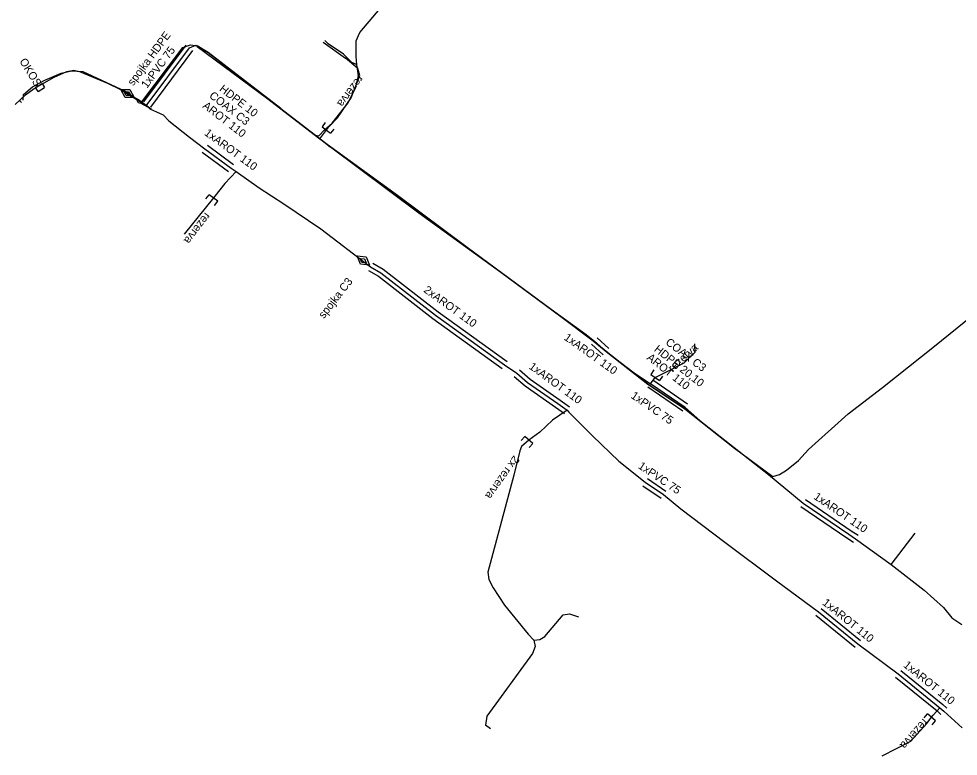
# Model space of a CAD drawing. Extents: x -651943 to -618711, y -1138561 to -1100552.
# Drawn here: x -648800.9 to -648712.9, y -1112060.5 to -1111991.5 of the extents above; entities that cross this region are included whole.
import ezdxf

# ---------------------------------------------------------------- set-up
doc = ezdxf.new("R2010")
doc.units = 0
for name, color, linetype in [('KT optika', 7, 'Continuous'), ('KT trasa', 7, 'Continuous'), ('KT zařízení', 7, 'Continuous')]:
    doc.layers.add(name, color=color, linetype=linetype)

# ---------------------------------------------------------------- blocks, each defined once
blk = doc.blocks.new('TVSPO_1')
at = {"layer": 'KT zařízení'}
for p, q in [((-0.074, 0.0016), (-0.0005, 0.0439)), ((-0.0005, -0.0409), (-0.074, 0.0016)), ((-0.0353, -0.0001), (0, 0.0203)), ((-0.0005, 0.0439), (0.0728, 0.0015)), ((0.0728, 0.0015), (-0.0005, -0.0409)), ((0, 0.0203), (0.0353, 0.0001)), ((0.0353, 0.0001), (0, -0.0204)), ((0, -0.0204), (-0.0353, -0.0001))]:
    blk.add_line(p, q, dxfattribs=at)
blk = doc.blocks.new('TVREZ')
at = {"layer": 'KT zařízení'}
for p, q in [((-0.05, 0.05), (0, 0.05)), ((0, -0.05), (0, 0.05)), ((-0.05, -0.05), (0, -0.05))]:
    blk.add_line(p, q, dxfattribs=at)

msp = doc.modelspace()

# ---------------------------------------------------------------- linework, layer by layer
at = {"layer": 'KT optika'}
for p, q in [((-648768.94, -1111992.78), (-648764.88, -1111988)), ((-648769.26, -1111993.55), (-648768.94, -1111992.78)), ((-648789.46, -1111999.38), (-648785.51, -1111994.17)), ((-648785.51, -1111994.17), (-648784.78, -1111993.94)), ((-648784.78, -1111993.94), (-648784.16, -1111994.01)), ((-648784.16, -1111994.01), (-648783.14, -1111994.66)), ((-648772.219, -1111993.533), (-648771.91, -1111993.85)), ((-648770.46, -1111994.81), (-648771.91, -1111993.85)), ((-648769.26, -1111995.02), (-648769.26, -1111993.55)), ((-648783.14, -1111994.66), (-648776.34, -1111999.9)), ((-648769.68, -1111995.57), (-648770.46, -1111994.81)), ((-648769.22, -1111995.76), (-648769.26, -1111995.02)), ((-648769.22, -1111995.76), (-648769.68, -1111995.57)), ((-648769.07, -1111996.82), (-648769.22, -1111995.76)), ((-648798.44, -1111997.23), (-648796.9, -1111996.58)), ((-648796.9, -1111996.58), (-648795.93, -1111996.35)), ((-648795.93, -1111996.35), (-648794.87, -1111996.44)), ((-648794.87, -1111996.44), (-648790.92, -1111998.27)), ((-648769.29, -1111997.88), (-648769.07, -1111996.82)), ((-648799.61, -1111997.87), (-648798.44, -1111997.23)), ((-648800.48, -1111999.12), (-648800.45, -1111998.58)), ((-648800.45, -1111998.58), (-648799.61, -1111997.87)), ((-648790.92, -1111998.27), (-648789.93, -1111998.92)), ((-648770.01, -1111999.37), (-648769.29, -1111997.88)), ((-648789.93, -1111998.92), (-648789.69, -1111999.33)), ((-648789.93, -1111998.92), (-648789.68, -1111999.05)), ((-648789.69, -1111999.33), (-648789.46, -1111999.38)), ((-648789.68, -1111999.05), (-648788.48, -1111999.91)), ((-648771.51, -1112001.26), (-648770.01, -1111999.37)), ((-648776.34, -1111999.9), (-648773.09, -1112002.39)), ((-648772.25, -1112001.89), (-648771.51, -1112001.26)), ((-648772.78, -1112002.44), (-648772.25, -1112001.89)), ((-648773.09, -1112002.39), (-648771.7, -1112003.47)), ((-648773.09, -1112002.39), (-648772.78, -1112002.44)), ((-648771.7, -1112003.47), (-648771.69, -1112003.47)), ((-648771.69, -1112003.47), (-648763.4, -1112009.67)), ((-648763.4, -1112009.67), (-648755.73, -1112015.2)), ((-648755.73, -1112015.2), (-648750.09, -1112019.36)), ((-648715.08, -1112022.15), (-648705.95, -1112014.71)), ((-648750.09, -1112019.36), (-648747.06, -1112021.63)), ((-648747.06, -1112021.63), (-648745.69, -1112022.75)), ((-648719.96, -1112026), (-648715.08, -1112022.15)), ((-648745.69, -1112022.75), (-648741.96, -1112025.7)), ((-648741.96, -1112025.7), (-648738.48, -1112028)), ((-648723.19, -1112028.48), (-648719.96, -1112026)), ((-648738.48, -1112028), (-648733.82, -1112031.7)), ((-648726.89, -1112031.82), (-648723.19, -1112028.48)), ((-648733.82, -1112031.7), (-648730.23, -1112034.35)), ((-648727.84, -1112032.84), (-648726.89, -1112031.82)), ((-648728.96, -1112033.73), (-648727.84, -1112032.84)), ((-648729.63, -1112034.15), (-648728.96, -1112033.73)), ((-648730.23, -1112034.35), (-648729.63, -1112034.15))]:
    msp.add_line(p, q, dxfattribs=at)
at = {"layer": 'KT trasa'}
for p, q in [((-648768.94, -1111992.78), (-648764.88, -1111988)), ((-648769.26, -1111993.55), (-648768.94, -1111992.78)), ((-648789.46, -1111999.38), (-648785.51, -1111994.17)), ((-648788.84, -1111999.51), (-648784.89, -1111994.21)), ((-648785.51, -1111994.17), (-648784.78, -1111993.94)), ((-648784.89, -1111994.21), (-648784.31, -1111993.97)), ((-648784.78, -1111993.94), (-648784.16, -1111994.01)), ((-648784.31, -1111993.97), (-648784.18, -1111994.1)), ((-648784.18, -1111994.1), (-648777.66, -1111998.89)), ((-648784.16, -1111994.01), (-648783.14, -1111994.66)), ((-648772.366, -1111993.676), (-648770.28, -1111995.18)), ((-648772.219, -1111993.533), (-648771.91, -1111993.85)), ((-648770.46, -1111994.81), (-648771.91, -1111993.85)), ((-648769.26, -1111995.02), (-648769.26, -1111993.55)), ((-648783.14, -1111994.66), (-648776.34, -1111999.9)), ((-648769.68, -1111995.57), (-648770.46, -1111994.81)), ((-648769.22, -1111995.76), (-648769.26, -1111995.02)), ((-648769.11, -1111996.14), (-648770.28, -1111995.18)), ((-648769.22, -1111995.76), (-648769.68, -1111995.57)), ((-648769.07, -1111996.82), (-648769.22, -1111995.76)), ((-648798.44, -1111997.23), (-648796.9, -1111996.58)), ((-648797.56, -1111996.95), (-648796.37, -1111996.44)), ((-648796.9, -1111996.58), (-648795.93, -1111996.35)), ((-648796.37, -1111996.44), (-648795.71, -1111996.3)), ((-648795.93, -1111996.35), (-648794.87, -1111996.44)), ((-648795.71, -1111996.3), (-648795.18, -1111996.42)), ((-648795.18, -1111996.42), (-648792.57, -1111997.53)), ((-648794.87, -1111996.44), (-648790.92, -1111998.27)), ((-648769.74, -1111998.9), (-648768.94, -1111996.79)), ((-648769.29, -1111997.88), (-648769.07, -1111996.82)), ((-648768.94, -1111996.79), (-648769.11, -1111996.14)), ((-648799.61, -1111997.87), (-648798.44, -1111997.23)), ((-648799.43, -1111998.03), (-648797.56, -1111996.95)), ((-648792.57, -1111997.53), (-648791.28, -1111998.14)), ((-648801.22, -1111999.52), (-648800.26, -1111998.61)), ((-648800.48, -1111999.12), (-648800.45, -1111998.58)), ((-648800.45, -1111998.58), (-648799.61, -1111997.87)), ((-648800.26, -1111998.61), (-648799.43, -1111998.03)), ((-648791.28, -1111998.14), (-648789.41, -1111999.29)), ((-648790.92, -1111998.27), (-648789.93, -1111998.92)), ((-648770.01, -1111999.37), (-648769.29, -1111997.88)), ((-648800.815, -1111999.136), (-648800.621, -1111999.34)), ((-648789.93, -1111998.92), (-648789.69, -1111999.33)), ((-648789.93, -1111998.92), (-648789.68, -1111999.05)), ((-648789.69, -1111999.33), (-648789.46, -1111999.38)), ((-648789.68, -1111999.05), (-648788.48, -1111999.91)), ((-648789.41, -1111999.29), (-648788.92, -1111999.62)), ((-648788.92, -1111999.62), (-648788.84, -1111999.51)), ((-648777.66, -1111998.89), (-648772.67, -1112002.74)), ((-648771.51, -1112001.26), (-648770.01, -1111999.37)), ((-648771.01, -1112000.76), (-648769.74, -1111998.9)), ((-648788.92, -1111999.62), (-648788.59, -1111999.92)), ((-648788.59, -1111999.92), (-648787.65, -1112000.37)), ((-648787.65, -1112000.37), (-648787.35, -1112000.48)), ((-648776.34, -1111999.9), (-648773.09, -1112002.39)), ((-648787.35, -1112000.48), (-648786.83, -1112001.05)), ((-648786.83, -1112001.05), (-648784.9, -1112002.57)), ((-648772.25, -1112001.89), (-648771.51, -1112001.26)), ((-648771.83, -1112001.59), (-648771.01, -1112000.76)), ((-648772.78, -1112002.44), (-648772.25, -1112001.89)), ((-648772.67, -1112002.74), (-648771.83, -1112001.59)), ((-648784.9, -1112002.57), (-648783.45, -1112003.66)), ((-648773.09, -1112002.39), (-648771.7, -1112003.47)), ((-648773.09, -1112002.39), (-648772.78, -1112002.44)), ((-648772.67, -1112002.74), (-648765.41, -1112008.01)), ((-648783.45, -1112003.66), (-648780.99, -1112005.46)), ((-648771.7, -1112003.47), (-648771.69, -1112003.47)), ((-648771.69, -1112003.47), (-648763.4, -1112009.67)), ((-648780.99, -1112005.46), (-648780.51, -1112005.78)), ((-648780.51, -1112005.78), (-648781.57, -1112006.92)), ((-648780.51, -1112005.78), (-648778.35, -1112007.33)), ((-648781.57, -1112006.92), (-648782.52, -1112008.11)), ((-648778.35, -1112007.33), (-648776.06, -1112008.82)), ((-648782.644, -1112008.263), (-648785.384, -1112011.651)), ((-648782.52, -1112008.11), (-648782.644, -1112008.263)), ((-648765.41, -1112008.01), (-648758.89, -1112012.87)), ((-648776.06, -1112008.82), (-648772.58, -1112011.14)), ((-648763.4, -1112009.67), (-648755.73, -1112015.2)), ((-648772.58, -1112011.14), (-648767.92, -1112014.71)), ((-648758.89, -1112012.87), (-648751, -1112018.66)), ((-648767.92, -1112014.71), (-648766.96, -1112015.26)), ((-648766.96, -1112015.26), (-648761.84, -1112019.24)), ((-648755.73, -1112015.2), (-648750.09, -1112019.36)), ((-648715.08, -1112022.15), (-648705.95, -1112014.71)), ((-648751, -1112018.66), (-648747.74, -1112021.06)), ((-648761.84, -1112019.24), (-648755.37, -1112023.89)), ((-648750.09, -1112019.36), (-648747.06, -1112021.63)), ((-648747.74, -1112021.06), (-648746.95, -1112021.66)), ((-648747.06, -1112021.63), (-648745.69, -1112022.75)), ((-648746.95, -1112021.66), (-648745.86, -1112022.64)), ((-648737.51, -1112022.69), (-648737.537, -1112021.905)), ((-648719.96, -1112026), (-648715.08, -1112022.15)), ((-648745.86, -1112022.64), (-648743.23, -1112024.64)), ((-648745.69, -1112022.75), (-648741.96, -1112025.7)), ((-648738.56, -1112023.7), (-648737.51, -1112022.69)), ((-648755.37, -1112023.89), (-648754.22, -1112024.67)), ((-648740.27, -1112024.58), (-648738.56, -1112023.7)), ((-648754.22, -1112024.67), (-648753.21, -1112025.53)), ((-648743.23, -1112024.64), (-648741.71, -1112025.65)), ((-648741.71, -1112025.65), (-648741.26, -1112025.06)), ((-648741.26, -1112025.06), (-648740.27, -1112024.58)), ((-648753.21, -1112025.53), (-648750.38, -1112027.51)), ((-648741.96, -1112025.7), (-648738.48, -1112028)), ((-648738.46, -1112027.89), (-648741.71, -1112025.65)), ((-648723.19, -1112028.48), (-648719.96, -1112026)), ((-648750.38, -1112027.51), (-648749.52, -1112028.13)), ((-648749.52, -1112028.13), (-648750.88, -1112029.07)), ((-648749.52, -1112028.13), (-648749.35, -1112028.3)), ((-648749.35, -1112028.3), (-648747.13, -1112030.54)), ((-648738.48, -1112028), (-648733.82, -1112031.7)), ((-648738.46, -1112027.89), (-648737.08, -1112029.09)), ((-648726.89, -1112031.82), (-648723.19, -1112028.48)), ((-648750.88, -1112029.07), (-648752.06, -1112030.19)), ((-648737.08, -1112029.09), (-648730.66, -1112034.16)), ((-648752.06, -1112030.19), (-648753.11, -1112030.93)), ((-648753.11, -1112030.93), (-648753.8, -1112031.53)), ((-648747.13, -1112030.54), (-648744.68, -1112032.91)), ((-648753.94, -1112031.92), (-648754.5, -1112034.2)), ((-648753.8, -1112031.53), (-648753.94, -1112031.92)), ((-648733.82, -1112031.7), (-648730.23, -1112034.35)), ((-648727.84, -1112032.84), (-648726.89, -1112031.82)), ((-648744.68, -1112032.91), (-648742.21, -1112034.87)), ((-648728.96, -1112033.73), (-648727.84, -1112032.84)), ((-648729.63, -1112034.15), (-648728.96, -1112033.73)), ((-648754.5, -1112034.2), (-648756.93, -1112043.29)), ((-648730.66, -1112034.16), (-648727.39, -1112036.83)), ((-648730.23, -1112034.35), (-648729.63, -1112034.15)), ((-648742.21, -1112034.87), (-648740.49, -1112036.03)), ((-648740.49, -1112036.03), (-648738.85, -1112037.37)), ((-648738.85, -1112037.37), (-648734.75, -1112040.48)), ((-648727.39, -1112036.83), (-648723.11, -1112039.75)), ((-648723.11, -1112039.75), (-648722.48, -1112040.16)), ((-648719.14, -1112042.59), (-648716.918, -1112039.628)), ((-648734.75, -1112040.48), (-648729.89, -1112044.11)), ((-648722.48, -1112040.16), (-648719.14, -1112042.59)), ((-648719.14, -1112042.59), (-648716.07, -1112044.99)), ((-648756.93, -1112043.29), (-648756.84, -1112043.97)), ((-648756.84, -1112043.97), (-648756.44, -1112044.75)), ((-648729.89, -1112044.11), (-648725.97, -1112047)), ((-648756.44, -1112044.75), (-648755.39, -1112046.38)), ((-648716.07, -1112044.99), (-648714.25, -1112046.6)), ((-648755.39, -1112046.38), (-648753.15, -1112049.11)), ((-648725.97, -1112047), (-648722.29, -1112049.99)), ((-648714.25, -1112046.6), (-648713.47, -1112047.58)), ((-648751.59, -1112049.32), (-648749.87, -1112047.3)), ((-648749.87, -1112047.3), (-648749.3, -1112047.2)), ((-648749.3, -1112047.2), (-648748.461, -1112047.463)), ((-648713.47, -1112047.58), (-648712.54, -1112048.2)), ((-648753.15, -1112049.11), (-648752.62, -1112049.67)), ((-648752.62, -1112049.67), (-648752.06, -1112049.59)), ((-648752.62, -1112049.67), (-648752.49, -1112050.24)), ((-648752.06, -1112049.59), (-648751.59, -1112049.32)), ((-648752.49, -1112050.24), (-648752.75, -1112050.92)), ((-648722.29, -1112049.99), (-648718.51, -1112052.81)), ((-648752.75, -1112050.92), (-648757.03, -1112056.78)), ((-648718.51, -1112052.81), (-648714.58, -1112055.99)), ((-648757.03, -1112056.78), (-648757.17, -1112057.61)), ((-648715.37, -1112056.879), (-648715.21, -1112056.67)), ((-648714.58, -1112055.99), (-648715.21, -1112056.67)), ((-648714.58, -1112055.99), (-648714.22, -1112056.32)), ((-648714.22, -1112056.32), (-648712.51, -1112057.85)), ((-648756.694, -1112057.968), (-648757.17, -1112057.61)), ((-648715.82, -1112057.47), (-648717.34, -1112059.13)), ((-648715.82, -1112057.47), (-648715.37, -1112056.879)), ((-648717.34, -1112059.13), (-648720.031, -1112060.52))]:
    msp.add_line(p, q, dxfattribs=at)
at = {"layer": 'KT zařízení'}
for p, q in [((-648768.94, -1111992.78), (-648764.88, -1111988)), ((-648769.26, -1111993.55), (-648768.94, -1111992.78)), ((-648785.51, -1111994.17), (-648789.46, -1111999.38)), ((-648789.16, -1111999.27), (-648785.21, -1111993.97)), ((-648785.51, -1111994.17), (-648784.78, -1111993.94)), ((-648783.14, -1111994.66), (-648784.16, -1111994.01)), ((-648770.46, -1111994.81), (-648771.91, -1111993.85)), ((-648769.26, -1111995.02), (-648769.26, -1111993.55)), ((-648788.519, -1111999.749), (-648784.569, -1111994.449)), ((-648776.34, -1111999.9), (-648783.14, -1111994.66)), ((-648769.68, -1111995.57), (-648770.46, -1111994.81)), ((-648769.22, -1111995.76), (-648769.26, -1111995.02)), ((-648769.68, -1111995.57), (-648769.22, -1111995.76)), ((-648769.07, -1111996.82), (-648769.22, -1111995.76)), ((-648798.44, -1111997.23), (-648796.9, -1111996.58)), ((-648796.9, -1111996.58), (-648795.93, -1111996.35)), ((-648795.93, -1111996.35), (-648794.87, -1111996.44)), ((-648794.87, -1111996.44), (-648790.92, -1111998.27)), ((-648769.29, -1111997.88), (-648769.07, -1111996.82)), ((-648799.61, -1111997.87), (-648798.44, -1111997.23)), ((-648799.31, -1111997.93), (-648798.693, -1111997.551)), ((-648798.693, -1111997.551), (-648798.46, -1111997.93)), ((-648800.48, -1111999.12), (-648800.45, -1111998.58)), ((-648800.45, -1111998.58), (-648799.61, -1111997.87)), ((-648799.077, -1111998.309), (-648799.31, -1111997.93)), ((-648799.077, -1111998.309), (-648798.46, -1111997.93)), ((-648790.92, -1111998.27), (-648789.93, -1111998.92)), ((-648770.01, -1111999.37), (-648769.29, -1111997.88)), ((-648789.93, -1111998.92), (-648789.69, -1111999.33)), ((-648789.69, -1111999.33), (-648789.46, -1111999.38)), ((-648789.46, -1111999.38), (-648788.48, -1111999.91)), ((-648771.51, -1112001.26), (-648770.01, -1111999.37)), ((-648776.34, -1111999.9), (-648773.09, -1112002.39)), ((-648772.25, -1112001.89), (-648771.51, -1112001.26)), ((-648772.78, -1112002.44), (-648772.25, -1112001.89)), ((-648773.09, -1112002.39), (-648772.78, -1112002.44)), ((-648773.09, -1112002.39), (-648771.69, -1112003.47)), ((-648783.213, -1112003.337), (-648780.753, -1112005.137)), ((-648771.69, -1112003.47), (-648763.4, -1112009.67)), ((-648783.686, -1112003.982), (-648781.226, -1112005.782)), ((-648763.4, -1112009.67), (-648755.73, -1112015.2)), ((-648767.721, -1112014.362), (-648766.739, -1112014.925)), ((-648768.118, -1112015.057), (-648767.18, -1112015.594)), ((-648766.739, -1112014.925), (-648761.6, -1112018.919)), ((-648755.73, -1112015.2), (-648750.09, -1112019.36)), ((-648715.08, -1112022.15), (-648705.95, -1112014.71)), ((-648767.18, -1112015.594), (-648762.079, -1112019.56)), ((-648761.6, -1112018.919), (-648755.136, -1112023.565)), ((-648762.079, -1112019.56), (-648755.603, -1112024.214)), ((-648750.09, -1112019.36), (-648747.06, -1112021.63)), ((-648746.682, -1112021.362), (-648745.592, -1112022.342)), ((-648747.217, -1112021.957), (-648746.127, -1112022.937)), ((-648745.69, -1112022.75), (-648747.06, -1112021.63)), ((-648719.96, -1112026), (-648715.08, -1112022.15)), ((-648741.96, -1112025.7), (-648745.69, -1112022.75)), ((-648754.479, -1112024.974), (-648753.456, -1112025.845)), ((-648753.96, -1112024.365), (-648752.963, -1112025.214)), ((-648753.456, -1112025.845), (-648750.604, -1112027.841)), ((-648752.963, -1112025.214), (-648750.155, -1112027.178)), ((-648738.48, -1112028), (-648741.96, -1112025.7)), ((-648738.233, -1112027.56), (-648741.483, -1112025.32)), ((-648738.686, -1112028.219), (-648741.936, -1112025.979)), ((-648723.19, -1112028.48), (-648719.96, -1112026)), ((-648750.155, -1112027.178), (-648749.286, -1112027.805)), ((-648750.604, -1112027.841), (-648749.753, -1112028.454)), ((-648738.48, -1112028), (-648733.82, -1112031.7)), ((-648726.89, -1112031.82), (-648723.19, -1112028.48)), ((-648733.82, -1112031.7), (-648730.23, -1112034.35)), ((-648727.84, -1112032.84), (-648726.89, -1112031.82)), ((-648728.96, -1112033.73), (-648727.84, -1112032.84)), ((-648729.63, -1112034.15), (-648728.96, -1112033.73)), ((-648741.986, -1112034.538), (-648740.266, -1112035.698)), ((-648730.23, -1112034.35), (-648729.63, -1112034.15)), ((-648742.433, -1112035.201), (-648740.713, -1112036.361)), ((-648727.164, -1112036.499), (-648722.898, -1112039.409)), ((-648727.615, -1112037.16), (-648723.321, -1112040.09)), ((-648722.898, -1112039.409), (-648722.261, -1112039.824)), ((-648723.321, -1112040.09), (-648722.698, -1112040.495)), ((-648725.717, -1112046.689), (-648722.037, -1112049.679)), ((-648726.222, -1112047.31), (-648722.542, -1112050.3)), ((-648718.761, -1112053.12), (-648714.844, -1112056.289)), ((-648718.258, -1112052.499), (-648714.315, -1112055.69)), ((-648714.315, -1112055.69), (-648713.949, -1112056.025)), ((-648714.844, -1112056.289), (-648714.49, -1112056.614))]:
    msp.add_line(p, q, dxfattribs=at)

# ---------------------------------------------------------------- block references
for name, p, xscale, yscale, rotation in [('TVSPO_1', (-648790.7, -1111998.5), 9.99999685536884, 9.999996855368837, -31.15346393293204), ('TVREZ', (-648772.066, -1112001.913), 10.000006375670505, 10.000006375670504, -126.9713901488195), ('TVREZ', (-648782.644, -1112008.263), 10.000001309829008, 10.000001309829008, 52.640883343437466), ('TVSPO_1', (-648768.61, -1112014.14), 9.999999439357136, 9.999999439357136, -36.7609878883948), ('TVREZ', (-648741.26, -1112025.06), 10.000002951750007, 10.000002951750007, -124.60701951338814), ('TVREZ', (-648753.11, -1112030.93), 10.000005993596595, 10.000005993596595, 48.72241375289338), ('TVREZ', (-648715.37, -1112056.879), 10.000005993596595, 10.000005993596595, 48.72241375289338)]:
    msp.add_blockref(name, p, dxfattribs=dict(at, xscale=xscale, yscale=yscale, rotation=rotation))

# ---------------------------------------------------------------- texts
for s, height, rotation, p in [('spojka HDPE', 0.74999, 53.30346, (-648790.167, -1111997.821)), ('1xPVC 75', 0.75, 53.30346, (-648788.877, -1111998.054)), ('OKOS', 0.75, 301.58219, (-648800.845, -1111995.458)), ('rezerva', 0.75, 233.03854, (-648769.09, -1111996.729)), ('HDPE 10', 0.75, 322.38258, (-648782.153, -1111998.18)), ('COAX C3', 0.75, 322.29582, (-648783.103, -1111998.818)), ('AROT 110', 0.75, 322.38258, (-648783.717, -1111999.759)), ('1xAROT 110', 0.75, 323.80679, (-648783.56, -1112002.319)), ('rezerva', 0.75, 232.55716, (-648783.422, -1112009.569)), ('spojka C3', 0.75, 52.00127, (-648772.299, -1112019.61)), ('2xAROT 110', 0.75, 323.99721, (-648763.014, -1112017.019)), ('1xAROT 110', 0.75, 324.52002, (-648749.869, -1112021.474)), ('COAX C3', 0.75, 322.86308, (-648740.351, -1112021.907)), ('HDPE 20,10', 0.75, 321.66007, (-648741.428, -1112022.546)), ('rezerva', 0.75, 42.08652, (-648739.653, -1112024.612)), ('AROT 110', 0.75, 321.66007, (-648742.113, -1112023.328)), ('1xAROT 110', 0.75, 323.99721, (-648753.152, -1112024.185)), ('1xPVC 75', 0.75, 325.42419, (-648743.603, -1112026.932)), ('2x rezerva', 0.75, 234.46232, (-648754.498, -1112032.316)), ('1xPVC 75', 0.75, 326.00354, (-648742.923, -1112033.511)), ('1xAROT 110', 0.75, 325.70062, (-648726.479, -1112036.383)), ('1xAROT 110', 0.75, 320.90614, (-648725.658, -1112046.27)), ('1xAROT 110', 0.75, 321.02159, (-648718.071, -1112052.102)), ('rezerva', 0.75, 228.72788, (-648716.175, -1112056.945))]:
    msp.add_text(s, height=height, rotation=rotation, dxfattribs=at).set_placement(p)

doc.saveas('drawing.dxf')
